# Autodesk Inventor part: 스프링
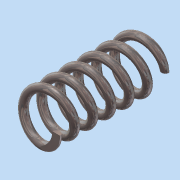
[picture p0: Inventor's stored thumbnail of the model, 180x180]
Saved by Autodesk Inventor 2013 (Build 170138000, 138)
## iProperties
Created: 2015-12
Part Number: 스프링
Material: 강철, 탄소
Document SubType Name: Modeling
Designer: Administrator
Density: 7.87 g/cm^3
Mass: 16.5231 g
Surface Area: 28.4697 cm^2
Volume: 2.0995 cm^3
Author: Administrator
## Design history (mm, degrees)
sketch "스케치1"
  geometry: L1 (0, 0)-(0, 42); L2 (0, 42)-(8, 42); L3 (0, 0)-(8, 0); C1 r 1.5 at (8, 0)
  constraints: 6 end point, 1 centre point, 1 coincident, 1 parallel, 1 perpendicular, 1 vertical
  dimensions: "d0" = 42 distance of L1.start L1.end (derived); "d1" = 8 distance of L1.end L2.end; "d2" = 8 distance of L1.start L3.end; "d3" = 1.5 radius of C1
feature "코일1" sketch "스케치1" pitch "d4" = 10; turns "d6" = 6; dims "d5" = 41.99999 (computed from d0), "d7" = 0, angle "d8" = 90 deg, angle "d9" = 90 deg, "d10" = 0, "d11" = 0
sketch "스케치2"
  geometry: L1 (42, 15)-(0, 15); L2 (0, 15)-(0, -15); L3 (0, -15)-(42, -15); L4 (42, -15)-(42, 15); 2 further points
  constraints: 8 end point, 2 parallel, 1 coincident, 1 horizontal, 1 midpoint, 1 perpendicular
  dimensions: "d12" = 42 distance of L2.end L3.end (derived); "d14" = 30 distance of L3.end L1.start
extrude "돌출1" sketch "스케치2" stored distance "d15" = 10; taper "d16" = 0 deg
node "솔리드1"
